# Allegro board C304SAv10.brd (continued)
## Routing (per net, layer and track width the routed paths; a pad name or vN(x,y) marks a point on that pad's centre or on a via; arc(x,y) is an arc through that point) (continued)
TS2_D6: length 93.3
  TOP w0.15: D9.J26 22,97 22,105.5 21.6,105.9 21.6,141 28.3,147.7 28.3,172.63 34.35,178.69 D31.38
TS2_D7: length 94.6
  TOP w0.15: v1(21.5,99.9) 21.5,105.3 21,105.8 21,141.1 27.9,148 27.9,172.9 33.72,178.72 D31.37 33.73,184.18 ; D9.J25 v1(22,96)
  MIDLAYER w0.15: v1(21.5,99.9) 21.5,96.5 v1(22,96)
TS2_VALID: length 95.2
  TOP w0.15: D9.H26 v1(21,97) ; D31.36 33.08,178.88 27.46,173.26 27.46,148.26 20.5,141.3 v1(20.5,99.8)
  MIDLAYER w0.15: v1(21,97) 20.5,97.5 v1(20.5,99.8)
  BOTTOM w0.15: R142.1 21.4,100.7 v1(20.5,99.8)
TXD_232: length 99
  TOP w0.2: v2(56.2,104.7) 56.2,113.4 58,115.2 64.6,115.2 65.95,113.85 D1.69 ; v2(61.6,57.9) 73.55,45.95 D18.11
  BOTTOM w0.2: v2(61.6,57.9) 61.6,80.1 54.8,86.9 54.8,103.3 v2(56.2,104.7)
N05536: length 4.7
  TOP w0.2: R14.2 90.25,118.75 D1.113
N05538: length 5.3
  TOP w0.2: R16.2 90.05,120.95 88.35,119.25 D1.114
N07829: length 16.9
  TOP w0.2: D1.32 44.25,124.75 G1.2
  BOTTOM w0.5: C12.2 G1.2
N08193: length 11.5
  TOP w0.2: G1.1 48.85,125.25 D1.31
  BOTTOM w0.5: C8.1 G1.1
N08983: length 9.7
  TOP w0.2: G2.1 51.05,122.75 D1.36
  BOTTOM w0.5: C17.2 G2.1
N09392: length 8.9
  TOP w0.2: D1.35 49.01,123.25 G2.2
  BOTTOM w0.5: G2.2 46.99,122.59 C14.1
N27514: length 4.4
  TOP w0.3: D1.38 v2(54.15,121.75)
  BOTTOM w0.3: R15.2 54.75,121.75 v2(54.15,121.75) 54.05,121.75 C7.2
N29811: length 4.4
  TOP w0.3: D1.29 54.35,126.25 v2(54.05,125.95)
  BOTTOM w0.3: C5.2 53.85,125.95 v2(54.05,125.95) 54.95,125.95 R13.2
N30543: length 2.3
  BOTTOM w0.3: R23.1 C19.2
N30727: length 2.3
  BOTTOM w0.3: R13.1 C6.2
N31299: length 2.3
  BOTTOM w0.3: R17.1 C13.2
N32037: length 2.3
  BOTTOM w0.3: R22.1 C16.2
N43106: length 4
  TOP w0.2: v2(58.15,129.35) 57.05,128.25 D1.25
  BOTTOM w0.2: v2(58.15,129.35) 58.15,130.05 R24.2
N44506: length 3
  TOP w0.2: D1.79 v2(70.95,113.65)
  BOTTOM w0.2: R28.2 70.95,114.1
  BOTTOM w0.3: v2(70.95,113.65) 70.95,114.15 70.55,114.55
N118230: length 4.3
  TOP w0.2: C46.1 R35.1 66.05,170.65 D5.38
N119725: length 3.5
  TOP w0.2: D6.38 v2(49.85,170.65)
  BOTTOM w0.2: v2(49.85,170.65) R36.1
  BOTTOM w0.5: R36.1 C47.1
N293237: length 11.8
  TOP w0.2: 74.5,97.3 G3.1 75.8,96 75.8,92.3 74.05,90.55 D8.47
  BOTTOM w0.5: G3.1 C68.1
N294666: length 14.1
  TOP w0.2: D8.46 75.35,90.05 79.65,94.35 G3.2
  BOTTOM w0.5: G3.2 C69.1
N300423: length 5.5
  TOP w0.2: R45.1 76.45,90.15 75.35,89.05 D8.44
N301796: length 5.2
  TOP w0.2: R44.1 76.35,88.55 D8.43
N302871: length 5.4
  TOP w0.2: D8.41 75.35,87.55 76.35,86.55 R46.1
N304860: length 5.7
  TOP w0.2: R47.1 76.55,85.35 74.85,87.05 D8.40
N306022: length 6
  TOP w0.2: D8.39 74.15,86.55 76.55,84.15 R48.1
N306487: length 6.3
  TOP w0.2: D8.38 73.45,86.05 76.55,82.95 R49.1
N307425: length 6.6
  TOP w0.2: R50.1 76.55,81.75 72.75,85.55 D8.37
N316976: length 2.5
  TOP w0.2: R51.1 66.25,81.65 D8.28
N334633: length 9.8
  TOP w0.5: T1.5 76.12,24.02 75.6,23.5 74.1,23.5 73.58,24.02 T1.7
  TOP w0.52: T1.5 76.12,29.38 C72.2
N338225: length 4.7
  BOTTOM w0.5: C71.2 R52.1 R55.1
N339802: length 4.6
  BOTTOM w0.5: C78.2 R57.1 R56.1
N340684: length 3.9
  TOP w0.5: T1.2 79.93,29.37 C79.2
N359542: length 1.9
  BOTTOM w0.5: R54.2 71.99,11.26 X6.14
N360160: length 1.8
  BOTTOM w0.5: R59.2 83.48,11.47 X6.12
N372108: length 4.2
  BOTTOM w0.5: R60.2 C85.1 R61.2
N373239: length 4
  BOTTOM w0.5: R63.2 R62.2 C86.1
N373968: length 8.9
  TOP w0.5: v3(77.39,16.4) T1.13 77.39,19.74 77.85,20.2 79.45,20.2 79.93,19.72 T1.15
  BOTTOM w0.5: R60.1 77.6,16.61 v3(77.39,16.4)
N375126: length 2.9
  TOP w0.5: T1.10 v3(73.58,16.4)
  BOTTOM w0.5: v3(73.58,16.4) 73.4,16.58 R61.1
N377910: length 14.7
  TOP w0.3: T1.9 72.31,16.6 73.55,15.36 73.55,14.35 75.4,12.5 75.4,5.4 X6.6
N379080: length 17.4
  TOP w0.3: X6.3 77.5,3 76,4.5 76,12.8 74.16,14.64 74.16,15.26 74.85,15.95 T1.11
N380455: length 13.4
  TOP w0.3: X6.2 79.1,5.1 79.1,15.3 78.66,15.74 T1.14
N381046: length 16
  TOP w0.3: T1.16 81.2,16.7 79.7,15.2 79.7,5.9 80.1,5.5 80.1,3.1 X6.1
N382236: length 4.9
  BOTTOM w0.5: X6.7 73,4 X6.8 73,6.1 R62.1
N383434: length 4.9
  BOTTOM w0.5: X6.5 77,4 X6.4 77,6.1 R63.1
N9171469: length 6.2
  TOP w0.2: D1.71 66.95,109.15 R4.1 64.85,107.05
N9173252: length 5.5
  TOP w0.2: D1.72 67.45,107.65 R5.1 66.85,107.05
N9248576: length 8.1
  TOP w0.3: D3.8 91.35,56.75 92.05,57.45 v3(92.05,60.75) R12.2 90.7,60.75
  BOTTOM w0.3: v3(92.05,60.75) R12.2
N9251784: length 11.8
  TOP w0.3: R11.2 86.35,62.05 85.05,63.35 81.85,63.35 80.45,64.75 X2.1 80.45,66.21
  TOP w0.5: R11.2 R12.1
N14977744: length 3
  BOTTOM w0.3: R15.1 53.95,116.95 C10.2
N16808315: length 165.6
  TOP w0.3: X4.2 84.7,12.65 84.7,34.6 81.3,38 v3(61.1,38) ; R26.1 R27.1 v3(45.3,133.9)
  MIDLAYER w0.3: v3(45.3,133.9) 45.3,118.5 50.2,113.6 v2(50.2,89.8)
  BOTTOM w0.3: v2(50.2,89.8) 50.2,63.4 61.1,52.5 v3(61.1,38)
N16825915: length 2.3
  TOP w0.3: HL3.1 v3(64.4,63.2)
  BOTTOM w0.3: v3(64.4,63.2) R20.2
N16825917: length 2.3
  TOP w0.3: v3(64.4,61) HL4.1
  BOTTOM w0.3: R21.2 v3(64.4,61)
N16825919: length 2.3
  TOP w0.3: HL1.1 v3(64.4,67.6)
  BOTTOM w0.3: v3(64.4,67.6) R18.2
N16825921: length 2.3
  TOP w0.3: v3(64.4,65.4) HL2.1
  BOTTOM w0.3: R19.2 v3(64.4,65.4)
N16864209: length 1.9
  TOP w0.3: v2(8.3,30.4) D11.4
  BOTTOM w0.3: R85.1 8.1,30.2 v2(8.3,30.4)
N16868983: length 4.2
  BOTTOM w0.5: C148.1 R77.1 R78.2
N16869942: length 3.9
  TOP w0.3: D11.1 10.25,30.5 v2(11,31.25) C149.2
  BOTTOM w0.3: C149.2 v2(11,31.25)
N16872327: length 4
  TOP w0.3: 9.6,29.45 D11.2 9.6,30.55 v2(8.9,31.25) C150.2
  BOTTOM w0.3: C150.2 v2(8.9,31.25)
N16882305: length 4.1
  TOP w0.4: R89.2 L6.2 C153.1
N16882306: length 4.1
  TOP w0.4: C152.1 L5.2 R88.2
N16882340: length 6.6
  TOP w0.4: R89.1 L6.1 v2(8.9,23) 9.6,23.7 D11.11
  BOTTOM w0.4: L6.1 v2(8.9,23)
N16882850: length 6.7
  TOP w0.4: D11.12 10.25,23.75 v2(11,23) L5.1 R88.1
  BOTTOM w0.4: L5.1 v2(11,23)
N16891295: length 4.2
  TOP w0.4: X14.1 C152.2
N16896654: length 4.2
  BOTTOM w0.5: C160.1 R94.1 R92.2
N16896672: length 4.1
  TOP w0.4: C159.1 L8.2 R91.2
N16896674: length 4.1
  TOP w0.4: R90.2 L7.2 C158.1
N16896676: length 6.7
  TOP w0.4: 25.6,25.45 D12.11 25.6,23.7 v2(24.9,23) L8.1 R91.1
  BOTTOM w0.4: L8.1 v2(24.9,23)
N16896680: length 6.8
  TOP w0.4: 26.25,25.45 D12.12 26.25,23.75 v2(27,23) L7.1 R90.1
  BOTTOM w0.4: L7.1 v2(27,23)
N16896682: length 3.9
  TOP w0.3: D12.1 26.25,30.5 v2(27,31.25) C161.2
  BOTTOM w0.3: C161.2 v2(27,31.25)
N16896719: length 3.9
  TOP w0.3: C162.2 v2(24.9,31.25) 25.6,30.55 D12.2
  BOTTOM w0.3: C162.2 v2(24.9,31.25)
N16896823: length 2
  TOP w0.3: v2(24.3,30.4) D12.4 24.3,29.45
  BOTTOM w0.3: R95.1 24.1,30.2 v2(24.3,30.4)
N16896879: length 4.2
  TOP w0.4: X15.1 C158.2
N16897851: length 4.2
  BOTTOM w0.5: R100.2 R102.1 C168.1
N16897869: length 4.1
  TOP w0.4: C167.1 L10.2 R99.2
N16897871: length 4.1
  TOP w0.4: C166.1 L9.2 R98.2
N16897873: length 6.6
  TOP w0.4: D13.11 41.6,23.7 v2(40.9,23) L10.1 R99.1
  BOTTOM w0.4: L10.1 v2(40.9,23)
N16897877: length 6.7
  TOP w0.4: D13.12 42.25,23.75 v2(43,23) L9.1 R98.1
  BOTTOM w0.4: L9.1 v2(43,23)
N16897879: length 3.9
  TOP w0.3: C169.2 v2(43,31.25) 42.25,30.5 D13.1
  BOTTOM w0.3: C169.2 v2(43,31.25)
N16897916: length 3.9
  TOP w0.3: C170.2 v2(40.9,31.25) 41.6,30.55 D13.2
  BOTTOM w0.3: C170.2 v2(40.9,31.25)
N16898020: length 1.9
  TOP w0.3: D13.4 v2(40.3,30.4)
  BOTTOM w0.3: R103.1 40.1,30.2 v2(40.3,30.4)
N16898076: length 4.2
  TOP w0.4: X16.1 C166.2
N16905369: length 4.2
  BOTTOM w0.5: R108.2 R110.1 C176.1
N16905379: length 4.1
  TOP w0.4: R106.2 L12.2 C174.1
N16905381: length 4.1
  TOP w0.4: C175.1 L11.2 R107.2
N16905399: length 6.6
  TOP w0.4: R106.1 L12.1 v2(56.9,23) 57.6,23.7 D14.11
  BOTTOM w0.4: L12.1 v2(56.9,23)
N16905403: length 6.7
  TOP w0.4: D14.12 58.25,23.75 v2(59,23) L11.1 R107.1
  BOTTOM w0.4: L11.1 v2(59,23)
N16905405: length 3.9
  TOP w0.3: D14.1 58.25,30.5 v2(59,31.25) C177.2
  BOTTOM w0.3: C177.2 v2(59,31.25)
N16905419: length 3.9
  TOP w0.3: D14.2 57.6,30.55 v2(56.9,31.25) C178.2
  BOTTOM w0.3: C178.2 v2(56.9,31.25)
N16905542: length 1.9
  TOP w0.3: D14.4 v2(56.3,30.4)
  BOTTOM w0.3: R111.1 56.1,30.2 v2(56.3,30.4)
N16905596: length 4.2
  TOP w0.4: X17.1 C175.2
N16942301: length 6.9
  TOP w0.3: D15.4 v3(19.45,183.7)
  BOTTOM w0.3: R79.1 C133.1 ; C133.1 v3(19.45,183.7) ; C133.1 R80.2
N16942461: length 2.9
  TOP w0.3: D15.5 v3(21.15,187.1)
  BOTTOM w0.3: R82.1 v3(21.15,187.1)
N16942511: length 2.3
  TOP w0.5: HL6.1 14.87,142.43 R81.2
N16948660: length 2.3
  TOP w0.3: R83.2 66.1,70.97 HL7.1
N16978661: length 2.2
  TOP w0.4: v3(8.9,14.1) C153.2
  BOTTOM w0.4: C153.2 v3(8.9,14.1)
N16984500: length 2.1
  TOP w0.4: C167.2 R116.1
N16986460: length 2.1
  TOP w0.4: C174.2 R117.1
N17223725: length 4.8
  TOP w0.2: D1.84 73.45,108.95 73,108.5 R130.2
N17224583: length 6.6
  TOP w0.2: D1.85 73.95,106.85 73.5,106.4 R129.2
N17225441: length 8.3
  TOP w0.2: R128.2 73.7,105.1 74.45,105.85 D1.86
N17226299: length 9.8
  TOP w0.2: D1.87 74.95,104.95 73.8,103.8 R127.2
N17227157: length 11.3
  TOP w0.2: R126.2 73.7,102.5 75.45,104.25 D1.88
N17239189: length 11.7
  BOTTOM w0.2: R121.1 29.1,206.2 29.1,212.6 28.4,213.3 26.54,213.3 X1.A7
N17239190: length 9.3
  BOTTOM w0.2: X1.A6 21.6,213.3 R122.1
N17245894: length 2.4
  TOP w0.3: 27.6,52.93 27.67,53 27.73,53 ; 27.73,53 R84.2 ; 27.73,53 HL8.1
N17253757: length 7.2
  BOTTOM w0.2: X1.B7 26.6,210.7 26.6,206.7 R123.1
N17253758: length 6.9
  BOTTOM w0.2: R124.1 24,206.1 24,210.76 X1.B6
N17260250: length 3.8
  BOTTOM w0.2: R125.1 25.34,205.96 X1.C7
N17338881: length 3.5
  TOP w0.3: D18.12 80.72,44.68 R132.2
N17347251: length 2.7
  TOP w0.2: D18.10 84.19,47.2 v3(82.7,47.2)
  BOTTOM w0.2: R133.2 v3(82.7,47.2)
N17354165: length 4.6
  TOP w0.3: D18.5 92.38,44.68 C180.1
N17355489: length 4.1
  TOP w0.3: D18.4 93.51,43.41 C180.2
N17356153: length 4.2
  TOP w0.3: D18.3 93.36,42.14 C181.1
N17358824: length 4.1
  TOP w0.3: D18.1 93.5,39.6 C181.2
N17377653: length 3.2
  TOP w0.3: D18.2 v3(88.4,40.87)
  BOTTOM w0.3: v3(88.4,40.87) 87.93,40.87 C183.1
N17383951: length 2.7
  TOP w0.3: D18.6 v3(88.4,45.95)
  BOTTOM w0.3: v3(88.4,45.95) 87.15,45.95 C184.1
N17388205: length 16.8
  TOP w0.2: D18.14 85.76,42.14 86.8,41.1 86.8,33.1 X18.1
N17389740: length 13.2
  TOP w0.2: X18.3 87.7,37.28 87.7,41.8 86.09,43.41 D18.13
N17391601: length 4.4
  TOP w0.3: R134.1 92.92,47.22 D18.7
N17552645: length 3.1
  TOP w0.3: D28.4 C219.1
N17552715: length 10.4
  TOP w0.3: D28.8 40.15,46.85 v1(40.5,47.2) 40.2,47.5 D28.9
  TOP w1: L13.1 47.6,47.2 v1(40.5,47.2)
  vias: v3(46.4,43.8) v3(48.1,43.8) v3(49.8,43.8)
N17574922: length 2.1
  BOTTOM w0.3: C187.1 R136.2
N17574956: length 2.9
  TOP w0.2: G4.3 17.88,112.22 R69.1
N17575063: length 2.2
  BOTTOM w0.3: C186.1 R135.2
N17877624: length 1.9
  TOP w0.15: D9.H24 v1(21,94)
  BOTTOM w0.15: R71.1 21.4,94.4 v1(21,94)
N17882638: length 1.8
  TOP w0.15: D9.G15 v1(20,85)
  BOTTOM w0.15: v1(20,85) 20.1,84.9 R70.2
N17918549: length 1.4
  BOTTOM w0.15: C222.1 R142.2
N17918577: length 1.6
  TOP w0.15: R141.2 C223.1
N17986390: length 2.8
  TOP w0.15: D9.AE20 39,90 v1(40,90)
  BOTTOM w0.15: R74.1 v1(40,90)
N18029824: length 4
  TOP w0.15: D9.AB13 v1(36,84)
  BOTTOM w0.15: v1(36,84) 36,86.4 R72.1
N18049270: length 3.1
  TOP w0.15: D9.C13 v1(17,84)
  BOTTOM w0.15: v1(17,84) 16,85 R75.1
N18128293: length 1.4
  BOTTOM w0.15: R137.2 C188.1
N18128321: length 1.6
  TOP w0.15: R138.2 C189.1
N18384691: length 2.3
  TOP w0.3: v1(45.2,106.3) HL12.1
  BOTTOM w0.3: R139.2 v1(45.2,106.3)
N18384693: length 2.3
  TOP w0.3: HL9.1 v1(45.2,104)
  BOTTOM w0.3: v1(45.2,104) R25.2
N18384695: length 2.1
  TOP w0.3: v1(45.1,110.8) HL10.1
  BOTTOM w0.3: R41.2 v1(45.1,110.8)
N18384697: length 2.5
  TOP w0.3: HL11.1 v1(45.3,108.5)
  BOTTOM w0.3: v1(45.3,108.5) R42.2
N18408270: length 2.3
  TOP w0.3: HL5.1 42.9,133.77 R33.2
N168966681: length 2.1
  TOP w0.4: C159.2 R115.1
N176021771: length 1.9
  TOP w0.15: D9.H6 v1(22,76)
  BOTTOM w0.15: R73.2 21.6,76.4 v1(22,76)

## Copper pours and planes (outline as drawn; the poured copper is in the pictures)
+1.2VD on TOP: 51.1,54.4 51.1,60.8 44.7,60.8 44.7,54.4
+1.2VD on TOP: 33.3,63.2 33.3,61.6 40.2,61.6 40.2,63.2
+1.2VD on VCC: 40.18,45.6 34.6,51.18 34.6,52.98 31.28,56.3 17.18,56.3 15.7,57.78 15.7,81.42 17.58,83.3 21.28,83.3 22.7,84.72 22.7,89.92 23.08,90.3 34.12,90.3 34.3,90.12 34.3,78.7 20.92,78.7 20.3,78.08 20.3,69.02 24.02,65.3 53.8,65.3 53.8,46.68 52.72,45.6 ; 1 cut-out
+1.8VD on TOP: 39.75,146.15 39.75,141.25 49.35,141.25 49.35,146.15
+1.8VD on VCC: 43.58,112.5 42,114.08 42,116.02 42.98,117 43.82,117 45.92,114.9 61.58,114.9 64.3,117.62 64.3,129.98 62.18,132.1 56.12,132.1 54.6,130.58 54.6,130.6 52.98,130.6 52,131.58 52,139.58 50.48,141.1 40.38,141.1 39.2,142.28 39.2,145.32 40.18,146.3 53.12,146.3 59.42,140 63.08,140 65.48,142.4 68.32,142.4 69.2,141.52 69.2,137.92 70.12,137 75.78,137 78.08,139.3 84.42,139.3 85.1,138.62 85.1,137.28 84.42,136.6 79.42,136.6 76,133.18 76,124.32 78.72,121.6 84.42,121.6 85.4,120.62 85.4,119.88 84.82,119.3 70.22,119.3 63.42,112.5
+2.5VD on TOP: 54.2,73.3 54.2,69.9 61,69.9 61,73.3
+2.5VD on VCC: 24.18,65.7 20.7,69.18 20.7,77.92 21.08,78.3 34.3,78.3 34.3,75.42 35.42,74.3 40.42,74.3 41.3,73.42 41.3,71.52 41.82,71 44.08,71 44.7,71.62 44.7,73.02 45.08,73.4 60.22,73.4 61.1,72.52 61.1,69.4 55.12,69.4 53.8,68.08 53.8,65.7
+3.3VD on TOP: 7.4,154.45 7.2,154.25 25.4,154.25 25.4,165.1 7.4,165.1
+3.3VD on VCC: 2.4,0.9 2.4,40.6 58.58,40.6 61.5,43.52 61.5,72.68 60.38,73.8 44.92,73.8 44.3,73.18 44.3,71.78 43.92,71.4 41.98,71.4 41.7,71.68 41.7,73.58 40.58,74.7 35.58,74.7 34.7,75.58 34.7,90.28 34.28,90.7 22.92,90.7 22.3,90.08 22.3,84.88 21.12,83.7 17.42,83.7 15.3,81.58 15.3,57.62 17.02,55.9 31.12,55.9 34.2,52.82 34.2,51.2 8.08,51.2 7.7,51.58 7.7,142.12 9.88,144.3 21.78,144.3 23,145.52 23,147.48 21.88,148.6 12.28,148.6 8.1,152.78 8.1,180.22 10.68,182.8 13.08,182.8 14.1,183.82 14.1,185.68 12.98,186.8 10.08,186.8 7.4,189.48 7.4,205.42 9.68,207.7 16.08,207.7 16.7,208.32 16.7,219.1 96.6,219.1 96.6,0.9 ; 1 cut-out
+5VD on TOP: 14.9,186.45 13.8,186.45 13.8,185.65 8.4,185.65 8.4,182.45 10,182.45 10,183.6 9.95,183.65 14.9,183.65
+5VD on VCC: 2.4,41 2.4,219.1 16.3,219.1 16.3,208.48 15.92,208.1 9.52,208.1 7,205.58 7,189.32 9.92,186.4 12.82,186.4 13.7,185.52 13.7,183.98 12.92,183.2 10.52,183.2 7.7,180.38 7.7,152.62 12.12,148.2 21.72,148.2 22.6,147.32 22.6,145.68 21.62,144.7 9.72,144.7 7.3,142.28 7.3,51.42 7.92,50.8 34.42,50.8 40.02,45.2 52.88,45.2 54.2,46.52 54.2,67.92 55.28,69 61.1,69 61.1,43.68 58.42,41
GNDD on TOP (solid shape): 27.03,69.8 27.36,69.68 27.72,69.7 27.75,69.66 27.77,69.62 27.77,68.94 17.06,58.23 15.83,58.23 15.83,58.6
GNDD on TOP (solid shape): 28.27,62.8 21.8,56.33 20.75,56.33 20.46,57.74 19.09,58.2 28.27,67.39
GNDD on TOP (solid shape): 75.65,16.22 76,16.11 76.37,16.14 76.95,15.44 77.86,15.46 77.86,15.41 78.3,14.97 78.3,6.1 78.14,5.98 78,5.83 77.46,6.22 76.8,6.29 76.8,13.13 74.98,14.95 75.65,15.62
GNDD on TOP (solid shape): 65.68,50.15 66.56,50.68 73.29,43.95 77.01,43.95 77.01,41.19 81.99,41.19 81.99,43.88 82.69,43.88 82.57,43.3 82.82,42.77 82.56,42.14 82.82,41.51 82.59,41.1 82.59,40.64 82.38,40.59 82.18,40.5 73.47,40.5 64.33,49.65 64.76,50.1 64.83,50.73
GNDD on TOP (solid shape): outline of 8188 points within 3.15,1.15 95.85,203.68
GNDD on BOTTOM (solid shape): 46.36,149.77 43.41,149.77 42.83,150.35 45.79,150.35
GNDD on BOTTOM (solid shape): 71.75,128.39 71.75,118.81 68.65,121.91 68.65,128.51 62.01,135.15 64.99,135.15
GNDD on BOTTOM (solid shape): 71.65,146.19 69.89,146.19 69.89,142.12 69.76,142 69.65,141.87 69.65,147.01 66.61,150.05 61.74,150.05 61.74,152.15 65.69,152.15
GNDD on BOTTOM (solid shape): 54.75,146.09 54.75,136.64 52.35,139.03 52.35,145.91 46.41,151.85 42.7,151.85 42.68,151.87 42.8,152.01 42.89,152.16 43.12,152.39 46.59,152.39 46.59,154.25
GNDD on BOTTOM (solid shape): 41.83,195.21 33.21,195.21 33.21,192.39 36,192.39 36,192.34 36.01,192.33 26.99,192.33 27.02,192.46 27.03,192.59 31.19,192.59 31.19,195.41 30.83,195.41 30.83,195.48 30.83,195.55 41.49,195.55
GNDD on BOTTOM (solid shape): 63.85,114.41 63.25,113.81 63.09,114.39 62.61,114.75 62.61,117.14 63.85,117.14
GNDD on BOTTOM (solid shape): 59.59,140.71 60.55,140.71 60.66,140.24 60.99,139.89 60.99,139.33 61.3,138.86 58.55,138.86 58.55,139.82 59.59,140.85
GNDD on BOTTOM (solid shape): 45.78,111.71 49.11,111.71 49.11,111.68 54.41,111.68 54.41,111.43 55.16,111.43 55.16,110.15 50.08,110.15 49.77,110.31 49.41,110.35 49.41,110.99 46.59,110.99 46.59,110.45 45.96,110.45 45.89,111.28 45.19,111.72 45.19,111.81 45.78,111.81
GNDD on BOTTOM (solid shape): 49.56,117.59 45.78,117.59 45.78,116.79 43.69,116.79 43.3,116.97 42.86,116.98 43.49,117.69 43.55,118.64 48.01,118.64 48.88,118.7 49.56,119.25
GNDD on BOTTOM (solid shape): 74.05,143.79 74.05,136.12 72.18,137.99 72.34,138.27 72.4,138.6 72.96,139.08 73,139.82 73.39,140.76 72.71,141.51 72.71,145.12
GNDD on BOTTOM (solid shape): 78.75,145.8 79.19,145.54 79.7,145.53 79.71,145.41 79.73,145.29 79.64,145.29 79.64,142.25 79,141.35 79.64,140.45 79.64,140.31 82.17,140.31 82.1,139.99 82.14,139.66 79.86,139.66 79.86,136.84 82.11,136.84 82.12,136.75 82.14,136.66 79.96,136.66 79.96,134.5 78.75,135.71
GNDD on BOTTOM (solid shape): 35.49,88.94 38.94,88.94 38.94,88.06 35.92,88.06 34.42,88.72 34.75,87.11 34.06,87.11 34.06,89.08 34.71,89.4 34.92,90.09 35.49,90.09
GNDD on BOTTOM (solid shape): 72.65,135.39 72.65,129.62 65.61,136.65 64.79,136.65 65.1,136.73 65.36,136.91 66,136.75 66.59,137.04 67.28,136.99 67.83,137.43 68.73,137.51 69.15,138.31 69.33,138.41 69.49,138.54
GNDD on BOTTOM (solid shape): 63.75,96.99 64.12,96.35 64.83,96.16 64.83,91.76 63.65,91.76 63.65,92.62 62.9,94.15 62.15,92.62 62.15,91.82 62.1,91.83 62.06,92.18 61.9,92.48 61.9,95.14
GNDD on BOTTOM (solid shape): 67.15,127.88 67.15,121.29 70.2,118.24 67.09,118.24 67.09,113.26 68.08,113.26 68.95,112.7 69.82,113.26 70.08,113.26 70.35,112.91 70.76,112.72 70.76,108.84 70.42,108.5 70.29,108.57 70.15,108.62 70.13,108.81 70.07,108.99 70.2,110.76 68.93,109.51 68.77,109.45 68.62,109.35 60.91,109.35 65.35,113.79 65.35,129.68
GNDD on BOTTOM (solid shape): 49.97,178.78 50.93,178.9 51.54,178.9 55.74,174.7 57.2,174.7 57.3,174.22 57.63,173.85 57.2,173.05 57.63,172.25 57.2,171.45 57.63,170.65 57.2,169.87 57.6,169.07 57.24,168.54 57.26,167.9 57.16,167.9 53.66,171.4 53.36,171.4 53.36,171.71 49.75,171.71 49.75,178.41 48.76,179.4 49.1,179.43 49.4,179.57
GNDD on BOTTOM (solid shape): 68.15,146.39 68.15,142.29 67.91,142.52 67.91,145.49 65.09,145.49 65.09,140.51 66.7,140.51 66.65,140.22 66.69,139.93 66.36,139.35 66.49,138.7 66.4,138.64 66.31,138.56 65.75,138.64 65.24,138.38 64.86,138.54 64.45,138.52 64.05,138.94 63.49,139.04 63.24,139.41 62.85,139.62 62.73,140.06 62.42,140.4 63.39,141.23 62.65,142.28 62.41,142.52 62.41,145.69 59.59,145.69 59.59,142.8 59.27,142.8 56.95,140.48 56.95,138.86 56.46,138.86 56.46,138.12 56.35,138.06 56.25,137.99 56.25,146.71 54.41,148.55 65.99,148.55
GNDD on BOTTOM (solid shape): 54.6,159.74 58.34,156 65.54,156 74.84,146.71 75.58,145.9 76.59,146.34 76.63,146.26 76.68,146.19 76.3,145.1 77.25,144.45 77.25,141.55 77.05,141.6 76.84,141.6 76.23,141.94 75.55,141.78 75.55,144.41 66.31,153.65 61.98,153.65 61.3,155.5 60.62,153.65 58.01,153.65 49.75,161.91 49.75,164.23 54.6,164.23
GNDD on BOTTOM (solid shape): outline of 171 points within 56.1,157.5 65.64,166.81
GNDD on BOTTOM (solid shape): 37.8,185.77 38.19,185.77 38.19,185.61 33.71,185.61 33.71,182.79 35.97,182.79 36.6,181.83 37.68,182.22 38.24,182.79 38.52,182.79 38.63,182.13 39.14,181.72 40.64,181.07 40.35,182.68 40.34,182.75 40.33,182.81 41.01,182.81 41.01,184.9 41.23,184.63 41.52,184.46 41.95,183.44 43.05,183.51 43.65,183.3 44.25,183.51 44.85,183.3 45.45,183.51 45.73,183.35 46.05,183.3 46.05,182.21 39.95,176.11 39.95,160.89 45.62,155.21 41.61,155.21 41.61,154.14 41.01,153.54 26.25,168.3 26.25,182.89 31.19,182.89 31.19,185.01 31.62,185.71 31.34,186.47 37.1,186.47
GNDD on BOTTOM (solid shape): outline of 371 points within 42.85,150.05 58.86,180.28
GNDD on BOTTOM (solid shape): 50.85,145.29 50.85,138.41 55.21,134.05 55.95,134.05 56.3,132.97 57.43,133 61.54,133 63.85,130.69 63.85,126.76 62.04,126.76 62.04,129.22 62.85,130.25 62.04,131.28 62.04,131.66 57.06,131.66 57.06,128.62 57.01,128.6 56.96,128.57 56.96,131.34 55.1,131.34 54.92,131.8 54.54,132.12 54.54,133.46 50.95,133.46 50.98,134.26 50.39,134.81 50.39,134.99 51.05,135.9 50.39,136.81 50.39,137.31 47.07,137.31 47.07,141.66 47.23,141.95 47.3,142.28 49.27,141.54 48.49,143.5 48.5,143.65 48.49,143.8 49.19,145.83 47.31,144.8 46.47,144.39 46.21,143.5 45.6,143.36 45.15,142.92 43.9,143.47 43,142.44 42.8,142.44 42.69,142.84 42.45,143.18 42.54,143.8 42.3,144.38 42.55,145.17 42.2,145.93 46.99,145.93 46.99,149.15
GNDD on BOTTOM (solid shape): outline of 405 points within 61.76,152.16 73.1,168.3
GNDD on BOTTOM (solid shape): outline of 488 points within 88.35,124.81 95.85,208.21
GNDD on BOTTOM (solid shape): outline of 1568 points within 57.49,98.27 92.85,180.13
GNDD on BOTTOM (solid shape): outline of 2270 points within 30.75,178 88.74,208.83
GNDD on MIDLAYER (solid shape): 7.78,151.77 7.84,151.86 7.95,151.84 8.52,151.26 8.52,98.73 8.46,98.64 8.35,98.66 7.78,99.24
GNDD on MIDLAYER (solid shape): 61.23,138.08 61.34,138.1 61.4,138 61.4,137.45 60.07,136.12 59.96,136.1 59.9,136.19 59.9,136.75
GNDD on MIDLAYER (solid shape): 70.6,190.95 76.2,190.95 77.03,190.12 77.05,190.01 76.95,189.95 70.4,189.95 66.47,193.88 66.45,193.99 66.55,194.05 67.5,194.05
GNDD on MIDLAYER (solid shape): 63.35,97 63.46,97.02 63.52,96.93 63.52,96.34 61.32,94.14 61.32,92.8 61.29,92.73 61.22,92.7 60.87,92.65 60.59,92.47 60.55,92.45 60.52,92.47 60.3,92.62 60.05,92.7 60,92.7 60,93.65
GNDD on MIDLAYER (solid shape): 48.55,207.84 48.66,207.86 48.72,207.77 48.72,206.74 29.95,187.96 29.84,187.94 29.78,188.03 29.78,188.36 40.54,199.12 40.56,199.12 41.3,199.56 41.19,200.41 41.16,200.44
GNDD on MIDLAYER (solid shape): 65.27,96.45 65.32,96.36 65.32,93.67 62.81,91.16 62.72,91.13 62.65,91.19 62.57,91.34 62.46,91.47 62.42,91.51 62.48,91.56 62.48,92.36 62.52,92.44 62.61,92.45 63.67,92.99 63.03,93.99 62.95,94.06 62.98,94.16 64.68,95.86 64.68,96.25 64.69,96.28 64.72,96.3 64.96,96.34 65.17,96.45
GNDD on MIDLAYER (solid shape): 63.13,135.08 63.24,135.1 63.3,135 63.3,114.45 63.12,114.28 63.04,114.25 62.97,114.29 61.73,114.42 61.86,113.18 61.9,113.11 61.88,113.03 60.36,111.51 60.29,111.48 60.22,111.51 59.08,111.52 59.09,110.38 59.12,110.31 59.09,110.24 54.67,105.82 54.56,105.8 54.5,105.89 54.5,112.05 61.9,119.45 61.9,125.95 63.1,127.15 63.1,135.05
GNDD on MIDLAYER (solid shape): outline of 150 points within 33.68,176.13 40.62,191.37
GNDD on MIDLAYER (solid shape): outline of 832 points within 81.83,77.08 92.9,186.76
GNDD on MIDLAYER (solid shape): outline of 28429 points within 1,1 98,219
GNDD on TOP: 34.7,46.4 37.7,46.4 37.7,51.2 34.7,51.2
GNDD on TOP, BOTTOM: 0,0 0,220 2,220 2,0
GNDD on TOP, BOTTOM: 97,0 97,220 99,220 99,0
GNDD on GND1: 97,219.5 98,219.5 98,0.5 97,0.5 2,0.5 1,0.5 1,219.5 2,219.5
GNDD on GND2: 98,219.5 98,0.5 98,0.5 2,0.5 2,0.5 1,0.5 1,219.5
(no net) on TOP: 96,1 3,1 3,219 96,219 ; 82 cut-outs
(no net) on BOTTOM: 3,1 3,219 96,219 96,1 ; 77 cut-outs
(no net) on MIDLAYER: 1,1 1,219 98,219 98,1 ; 85 cut-outs
N16942335 on TOP: 16.55,186.45 15.5,186.45 15.5,181.8 14.2,181.8 14.2,171.85 20.7,171.85 20.7,175.35 16.55,175.35
N17552715 on TOP: 38.3,47.7 44.7,47.7 44.7,49.4 51.1,49.4 51.1,43.3 44.7,43.3 44.7,46.7 38.3,46.7

Small or netless copper shapes (teardrops, artwork), in the pictures only: 1 on TOP, 6 on BOTTOM, 9 on MIDLAYER

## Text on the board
TOP: 20130524V10 | SUMAVISION EMR C304SAV10
Ref Des/Silkscreen Top: GND | RX | TX | WD | RST | SERAIL CODE AREA
NCLEGEND-1-6: FIGURE | SIZE | 0.3 | 0.4 | 0.5 | 0.7 | 0.889 | 0.9 | 0.97 | 1.0 | 2.0 | 2.2 | 2.9 | 3.0 | DRILL CHART: TOP to BOTTOM | ALL UNITS ARE IN MILLIMETERS | PLATED | NON-PLATED | QTY | 325 | 413 | 288 | 22 | 8 | 6 | 45 | 103 | 7 | 2
